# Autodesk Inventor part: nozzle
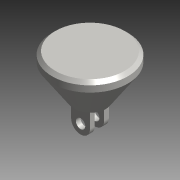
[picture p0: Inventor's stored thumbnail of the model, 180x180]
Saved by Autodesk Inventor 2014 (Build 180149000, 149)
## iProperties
Created: 2000-03
Part Number: nozzle
User Status: Reference File
Document SubType Name: Modeling
Designer: Peter Roberts
Density: 1 g/cm^3
Material: Generic
Appearance: Steel
Manager: Dave Ford
Company: Autodesk Inc.
Control State: 0
Master: False
Checked Out: False
Shininess: 0.0
Length Units: 11269
Angle Units: 11279
Time Units: 11290
Mass Units: 11284
Length Display Precision: 1
Angle Display Precision: 2
Compacted: True
PropertySet Name: Model Information
Density: 0.0
Volumn: 0.0
Area: 0.0
Subject: Tutorial #2 part file
Author: Peter Roberts
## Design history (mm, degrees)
body "Solid1"
sketch "Sketch1"
  geometry: L1 (0, 0)-(0, 27); L2 (0, 27)-(-24, 27); L3 (-24, 27)-(-24, 21); L4 (0, 0)-(-10, 0); L5 (-10, 0)-(-24, 21); L6 (-6, 0)-(-6, -10); L7 (6, -10)-(6, 0); L8 (6, 0)-(-6, 0); A1 r 6 centre (0, -10) between (-6, -10) and (6, -10)
  constraints: 16 end point, 4 perpendicular, 2 parallel, 2 point on circle, 2 tangent, 1 centre point, 1 point on line, 1 vertical
  dimensions: "d0" = 27 distance of L1.start L1.end; "d1" = 24 distance of L1.end L2.end; "d2" = 6 distance of L2.end L3.end; "d3" = 10 distance of L1.start L4.end; "d5" = 10 distance of L7.start L7.end; "d6" = 6 radius of A1; "d7" = 6 distance between parallel lines of L6 L1
node "Revolution1" dims "d4" = 90 deg
node "Extrusion1" dims "d8" = 12, "d9" = 0
node "Extrusion2" dims "d10" = 6, "d11" = 0
node "Chamfer1" dims "d12" = 2, "d13" = 2, "d20" = 45 deg
node "Hole1" dims "d14" = 6, "d15" = 4, "d16" = 2, "d17" = 60 deg, "d18" = 8, "d19" = 118 deg
sketch "Sketch2"
  geometry: A1 r 6 centre (0, -10) between (-6, -10) and (6, -10) reference; 1 further point
  constraints: 1 coincident
